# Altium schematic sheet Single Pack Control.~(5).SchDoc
size A
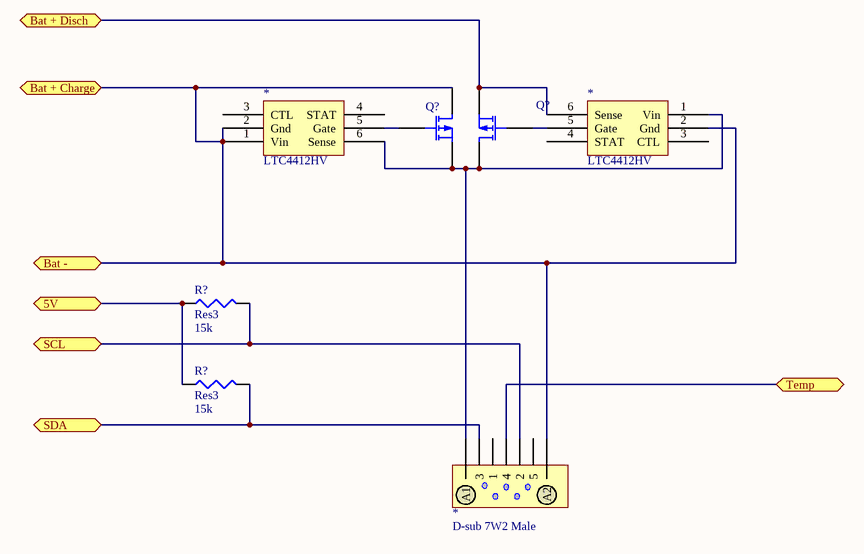
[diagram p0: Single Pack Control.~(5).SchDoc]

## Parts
(Parts that share a designator on the sheet are numbered #1, #2 ... from top to bottom, then left to right.)
*#1  LTC4412HV
*#2  LTC4412HV
*#3  D-sub 7W2 Male
Q?#1  MOSFET-P  [BCY-W3/B.8]  (value not drawn)
Q?#2  MOSFET-P  [BCY-W3/B.8]  (value not drawn)
R?#1  Res3  value 15k  [RESC1608L]
R?#2  Res3  value 15k  [RESC1608L]

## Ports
5V, Bat + Charge, Bat + Disch, Bat -, SCL, SDA, Temp

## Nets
5V: R?#1.1 R?#2.1 ; port 5V
Bat + Charge: *#1.1(Vin) *#1.2(Gnd) *#2.2(Gnd) *#3.7(A2) Q?#1.1(D) ; port Bat -, port Bat + Charge
Bat + Disch: *#2.6(Sense) Q?#2.3(S) ; port Bat + Disch
SCL: *#3.2 R?#1.2 ; port SCL
SDA: *#3.3 R?#2.2 ; port SDA
Temp: *#3.4 ; port Temp
Net*#1_5: *#1.5(Gate) Q?#1.2(G)
Net*#1_6: *#1.6(Sense) *#2.1(Vin) *#3.6(A1) Q?#1.3(S) Q?#2.1(D)
Net*#2_5: *#2.5(Gate) Q?#2.2(G)

Not connected (* = marked no-connect by the designer): *#1 3(CTL) 4(STAT); *#2 3(CTL) 4(STAT); *#3 1 5

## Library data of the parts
Q?#1 Q?#2 = MOSFET-P: P-Channel MOSFET
R?#1 R?#2 = Res3: Resistor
